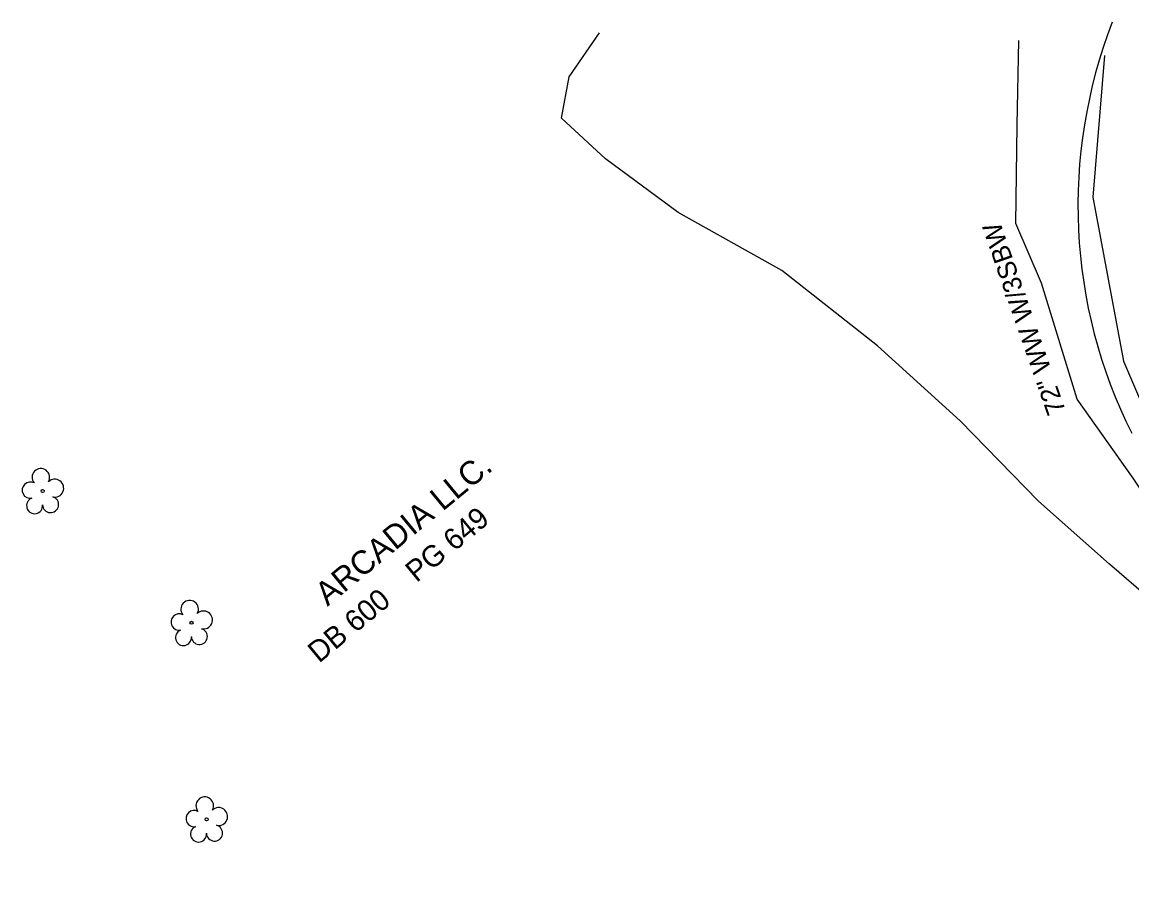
# Model space of a CAD drawing. Extents: x 1435573 to 1437263, y 981340 to 982884.
# Drawn here: x 1436101 to 1436335.7, y 982550 to 982734.5 of the extents above; entities that cross this region are included whole.
import ezdxf

# ---------------------------------------------------------------- set-up
doc = ezdxf.new("R2010")
doc.units = 0
for name, color, linetype in [('Exist Other Culture Fence Line', 7, 'Continuous'), ('Exist Other Culture Fence Line Text', 7, 'Continuous'), ('Exist Property Deed Book Text', 7, 'Continuous'), ('Exist Property Owner Text', 7, 'Continuous'), ('Exist Right of Way Line', 7, 'Continuous'), ('Exist Vegetation Tree CELL', 7, 'Continuous'), ('Exist Vegetation Woods Line', 7, 'Continuous')]:
    doc.layers.add(name, color=color, linetype=linetype)

msp = doc.modelspace()

# ---------------------------------------------------------------- linework, layer by layer
at = {"layer": 'Exist Other Culture Fence Line'}
msp.add_lwpolyline([(1436407.45, 982513.75), (1436396.08, 982537.77), (1436384.33, 982560.23), (1436367.33, 982589.31), (1436350.22, 982616.82), (1436336.01, 982638.12), (1436324.12, 982654.83), (1436316.59, 982679.36), (1436311.21, 982691.99), (1436311.43, 982712.74), (1436311.84, 982730.67)], dxfattribs=at)
at = {"layer": 'Exist Right of Way Line'}
msp.add_arc((1436431.59, 982695.7), 107.28, 158.7705, 206.6391, dxfattribs=at)
at = {"layer": 'Exist Vegetation Tree CELL'}
for p, q in [((1436105.31, 982635.41), (1436105.31, 982635.41)), ((1436136.8, 982607.52), (1436136.8, 982607.52)), ((1436139.99, 982565.95), (1436139.99, 982565.95))]:
    msp.add_line(p, q, dxfattribs=at)
for centre in [(1436105.31, 982635.41), (1436136.8, 982607.52), (1436139.99, 982565.95)]:
    msp.add_circle(centre, 0.326, dxfattribs=at)
for centre, radius, start, end in [((1436104.93, 982638.28), 1.86, 330.1651, 219.7134), ((1436107.86, 982635.99), 1.9, 257.1011, 134.1999), ((1436102.71, 982635.56), 1.73, 62.6636, 279.3457), ((1436103.61, 982632.28), 1.69, 111.5671, 6.231), ((1436106.99, 982632.51), 1.7, 181.2822, 74.56), ((1436136.41, 982610.39), 1.86, 330.1651, 219.7134), ((1436139.34, 982608.11), 1.9, 257.1011, 134.1999), ((1436134.19, 982607.67), 1.73, 62.6636, 279.3457), ((1436135.09, 982604.4), 1.69, 111.5671, 6.231), ((1436138.47, 982604.62), 1.7, 181.2822, 74.56), ((1436139.6, 982568.82), 1.86, 330.1651, 219.7134), ((1436137.38, 982566.1), 1.73, 62.6636, 279.3457), ((1436142.54, 982566.54), 1.9, 257.1011, 134.1999), ((1436138.28, 982562.83), 1.69, 111.5671, 6.231), ((1436141.66, 982563.05), 1.7, 181.2822, 74.56)]:
    msp.add_arc(centre, radius, start, end, dxfattribs=at)
at = {"layer": 'Exist Vegetation Woods Line'}
msp.add_lwpolyline([(1436329.94, 982727.52), (1436327.49, 982697.57), (1436333.96, 982662.84), (1436341.02, 982646.4), (1436348.03, 982632.21), (1436356.84, 982615.2), (1436357.01, 982604.5), (1436347.42, 982605.75), (1436330.99, 982619.92), (1436315.96, 982633.27), (1436299.42, 982650.22), (1436281.92, 982666.07), (1436261.65, 982682.01), (1436239.77, 982694.3), (1436224.35, 982705.66), (1436215.08, 982714.28), (1436216.7, 982722.96), (1436223.1, 982732.29)], dxfattribs=at)

# ---------------------------------------------------------------- texts
at = {"layer": 'Exist Other Culture Fence Line Text'}
msp.add_text('72" WW W/3SBW', height=4, rotation=109.1641, dxfattribs=at).set_placement((1436321.79, 982652.31))
at = {"layer": 'Exist Property Deed Book Text'}
msp.add_text('DB 600    PG 649', height=4.5, rotation=39.5399, dxfattribs=at).set_placement((1436163.77, 982598.86))
at = {"layer": 'Exist Property Owner Text'}
msp.add_text('ARCADIA LLC.', height=5, rotation=39.5399, dxfattribs=at).set_placement((1436165.57, 982610.89))

doc.saveas('drawing.dxf')
